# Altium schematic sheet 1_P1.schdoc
size 307 x 218 mm; Symbol: Drawing-Symbol_A4; Device: Drawing-Symbol_A4; @Project Name: PBT_PCB; @Page Count: 1; @Update Date: 2026-08-30; @Create Date: 2026-01-09; @Schematic Name: Schematic1_2; @Page No: 1; @Page Name: P1; Company: EasyEDA.com; Version: V1.0; Page Size: A4; @Create Time: 14:17:53; @Update Time: 10:38:52; Width: 1170; Height: 825; Region Start: 1; X Region Count: 6; Y Region Count: 4; Blade Width: 10; Title Block Position: 3; @Board Name: Sensor board_2s_lp
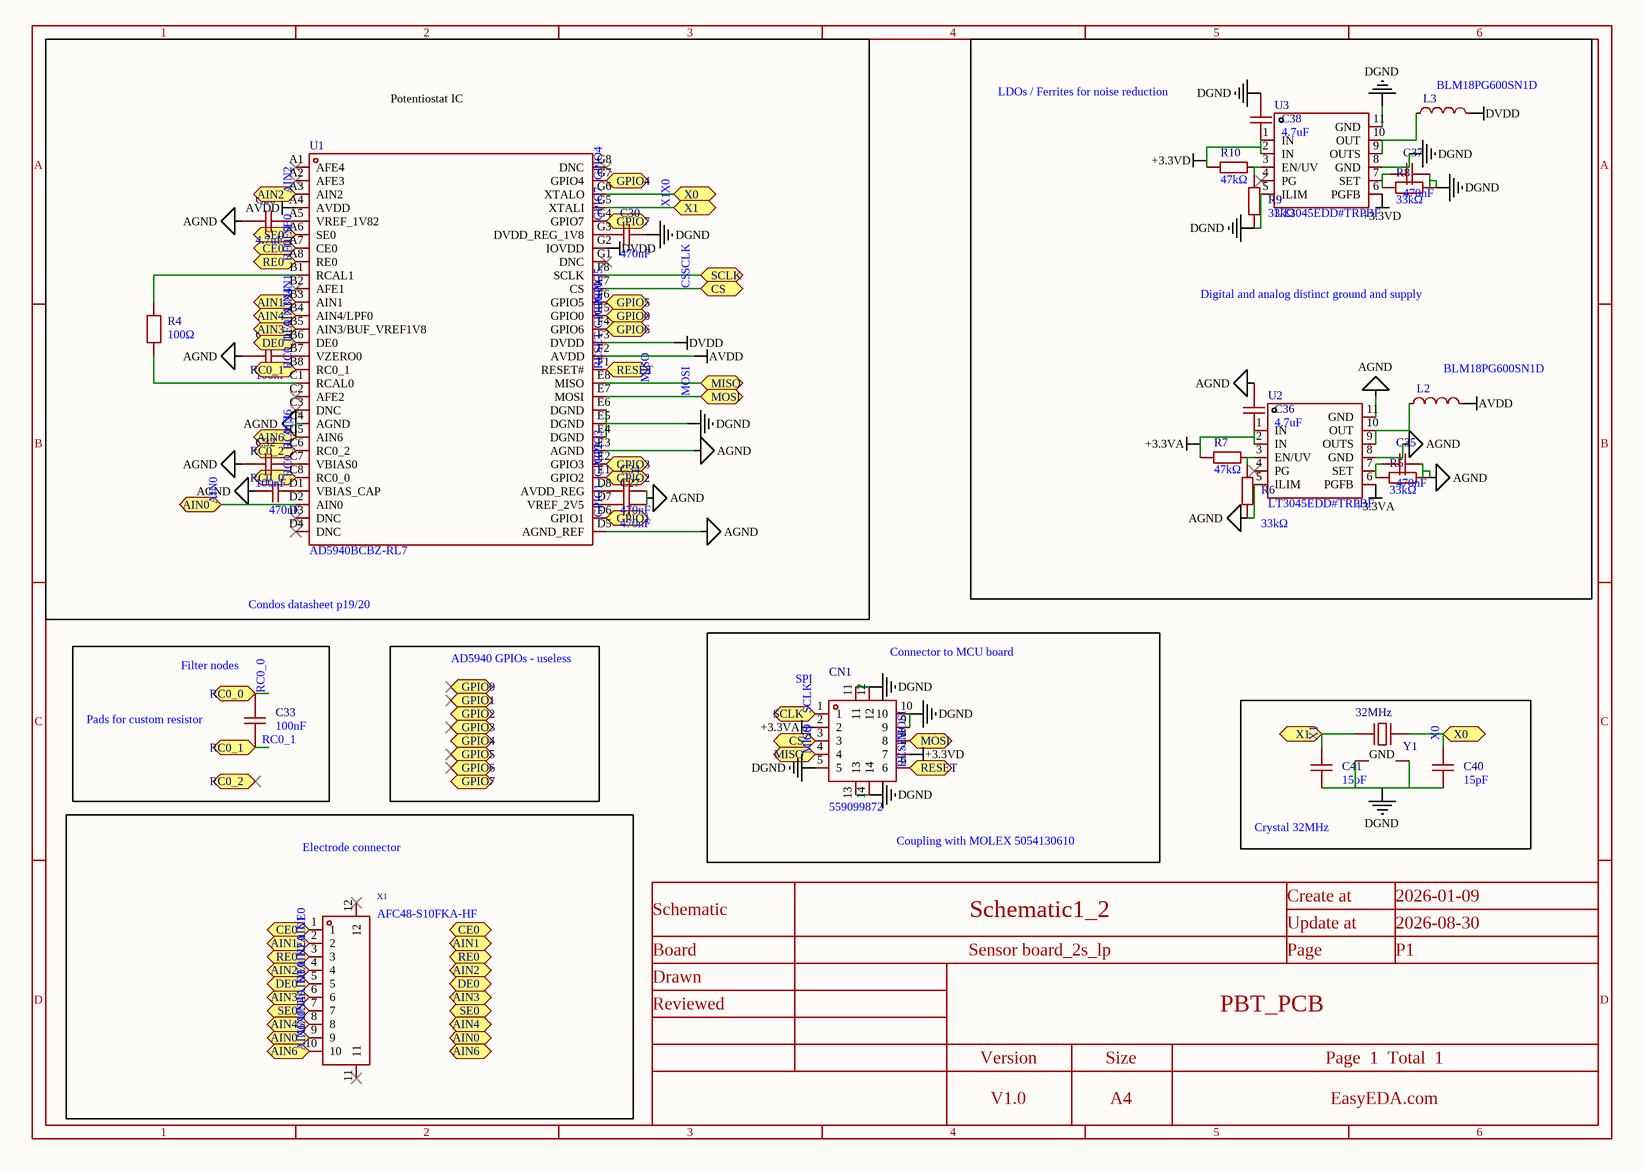
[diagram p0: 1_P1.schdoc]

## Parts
C27  470nF  [C0603]
C28  4.7uF  [C0402]
C29  470nF  [C0603]
C30  470nF  [C0603]
C31  100nF  [C0402]
C32  100nF  [C0402]
C33  100nF  [C0402]
C34  470nF  [C0603]
C35  470nF  [C0603]
C36  4.7uF  [C0402]
C37  470nF  [C0603]
C38  4.7uF  [C0402]
C40  15pF  [C0402]
C41  15pF  [C0402]
CN1  559099872  [CONN-SMD_559099872]
L2  BLM18PG600SN1D  [L0603]
L3  BLM18PG600SN1D  [L0603]
R4  100Ω  [R0603]
R5  33kΩ  [R0402]
R6  33kΩ  [R0402]
R7  47kΩ  [R0402]
R8  33kΩ  [R0402]
R9  33kΩ  [R0402]
R10  47kΩ  [R0402]
U1  AD5940BCBZ-RL7  [BGA-56_L4.2-W3.6-R8-C7-P0.40-TL]
U2  LT3045EDD#TRPBF  [DFN-10_L3.0-W3.0-P0.50-BL-EP]
U3  LT3045EDD#TRPBF  [DFN-10_L3.0-W3.0-P0.50-BL-EP]
X1  AFC48-S10FKA-HF  [FPC-SMD_AFC48-S10FKA-HF]
Y1  32MHz  [CRYSTAL-SMD_4P-L2.0-W1.6-BL]

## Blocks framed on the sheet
Crystal 32MHz: C40 C41 Y1
Electrode connector: X1

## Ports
AIN0 (bidir), AIN1 (bidir), AIN2 (bidir), AIN3 (bidir), AIN4 (bidir), AIN6 (bidir), CE0 (bidir), CS (bidir), DE0 (bidir), GPIO0 (bidir), GPIO1 (bidir), GPIO2 (bidir), GPIO3 (bidir), GPIO4 (bidir), GPIO5 (bidir), GPIO6 (bidir), GPIO7 (bidir), MISO (bidir), MOSI (bidir), RC0_0 (bidir), RC0_1 (bidir), RC0_2 (bidir), RE0 (bidir), RESET (bidir), SCLK (bidir), SE0 (bidir), X0 (bidir), X1 (bidir)

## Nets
+3.3VA: C36.2 CN1.2 R7.2 U2.1(IN) U2.2(IN) U2.6(PGFB)
+3.3VD: C38.2 CN1.7 R10.2 U3.1(IN) U3.2(IN) U3.6(PGFB)
AGND: C27.2 C28.1 C29.1 C31.1 C32.1 C34.2 C35.2 C36.1 R5.2 R6.1 U1.C4(AGND) U1.D5(AGND_REF) U1.E3(AGND) U2.5(ILIM) U2.8(GND) U2.11(GND)
AVDD: L2.2 U1.A4(AVDD) U1.F2(AVDD)
DGND: C30.2 C37.2 C38.1 C40.2 C41.2 CN1.5 CN1.9 CN1.10 CN1.11 CN1.12 CN1.13 CN1.14 R8.2 R9.1 U1.E4(DGND) U1.E5(DGND) U1.E6(DGND) U3.5(ILIM) U3.8(GND) U3.11(GND) Y1.2(GND) Y1.4(GND)
DVDD: L3.2 U1.F3(DVDD) U1.G2(IOVDD)
AIN0: U1.D2(AIN0) X1.9 ; port AIN0
AIN1: U1.B3(AIN1) X1.2 ; port AIN1
AIN2: U1.A3(AIN2) X1.4 ; port AIN2
AIN3: U1.B5(AIN3/BUF_VREF1V8) X1.6 ; port AIN3
AIN4: U1.B4(AIN4/LPF0) X1.8 ; port AIN4
AIN6: U1.C5(AIN6) X1.10 ; port AIN6
CE0: U1.A7(CE0) X1.1 ; port CE0
CS: CN1.3 U1.F7(CS) ; port CS
DE0: U1.B6(DE0) X1.5 ; port DE0
GPIO0: U1.F5(GPIO0) ; port GPIO0
GPIO1: U1.D6(GPIO1) ; port GPIO1
GPIO2: U1.E1(GPIO2) ; port GPIO2
GPIO3: U1.E2(GPIO3) ; port GPIO3
GPIO4: U1.G7(GPIO4) ; port GPIO4
GPIO5: U1.F6(GPIO5) ; port GPIO5
GPIO6: U1.F4(GPIO6) ; port GPIO6
GPIO7: U1.G4(GPIO7) ; port GPIO7
MISO: CN1.4 U1.E8(MISO) ; port MISO
MOSI: CN1.8 U1.E7(MOSI) ; port MOSI
RC0_0: C33.1 U1.C8(RC0_0) ; port RC0_0
RC0_1: C33.2 U1.B8(RC0_1) ; port RC0_1
RC0_2: U1.C6(RC0_2) ; port RC0_2
RE0: U1.A8(RE0) X1.3 ; port RE0
RESET: CN1.6 U1.F1(RESET#) ; port RESET
SCLK: CN1.1 U1.F8(SCLK) ; port SCLK
SE0: U1.A6(SE0) X1.7 ; port SE0
X0: C40.1 U1.G6(XTALO) Y1.3 ; port X0
X1: C41.1 U1.G5(XTALI) Y1.1 ; port X1
NetC27_1: C27.1 U1.D7(VREF_2V5)
NetC28_2: C28.2 U1.A5(VREF_1V82)
NetC29_2: C29.2 U1.D1(VBIAS_CAP)
NetC30_1: C30.1 U1.G3(DVDD_REG_1V8)
NetC31_2: C31.2 U1.B7(VZERO0)
NetC32_2: C32.2 U1.C7(VBIAS0)
NetC34_1: C34.1 U1.D8(AVDD_REG)
NetC35_1: C35.1 R5.1 U2.7(SET)
NetC37_1: C37.1 R8.1 U3.7(SET)
NetL2_1: L2.1 U2.9(OUTS) U2.10(OUT)
NetL3_1: L3.1 U3.9(OUTS) U3.10(OUT)
NetR4_1: R4.1 U1.B1(RCAL1)
NetR4_2: R4.2 U1.C1(RCAL0)
NetR6_2: R6.2 R7.1 U2.3(EN/UV)
NetR9_2: R9.2 R10.1 U3.3(EN/UV)

Not connected (* = marked no-connect by the designer): U1 A1(AFE4)* A2(AFE3)* B2(AFE1)* C2(AFE2)* C3(DNC)* D3(DNC)* D4(DNC)* G1(DNC)* G8(DNC)*; U2 4(PG)*; U3 4(PG)*; X1 11* 12*

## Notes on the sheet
- Potentiostat IC
- LDOs / Ferrites for noise reduction
- Digital and analog distinct ground and supply
- Condos datasheet p19/20
- (near CN1) Connector to MCU board
- (near C33) Filter nodes
- AD5940 GPIOs - useless
- (near CN1) SPI
- (near C33) Pads for custom resistor
- Coupling with MOLEX 5054130610

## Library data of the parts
C27 C29 C30 C34 C35 C37 = CL10B474KA8NNNC: Manufacturer: SAMSUNG(三星); Add into BOM: yes; Tolerance: ±10%; Voltage Rating: 25V; Temperature Coefficient: X7R
C28 C36 C38 = CL05A475MP5NRNC: Manufacturer: SAMSUNG(三星); Add into BOM: yes; Tolerance: ±20%; Voltage Rating: 10V; Temperature Coefficient: X5R
C31-C33 = CL05B104KO5NNNC: Manufacturer: SAMSUNG(三星); Add into BOM: yes; Tolerance: ±10%; Voltage Rating: 16V; Temperature Coefficient: X7R
C40 C41 = 0402CG150J500NT: Manufacturer: FH(风华); Add into BOM: yes; Tolerance: ±5%; Voltage Rating: 50V; Temperature Coefficient: C0G
CN1 = 559099872: Manufacturer: MOLEX; Add into BOM: yes; Pitch: 0.4mm; Current Rating: 300mA; Voltage Rating: 50V; System Fit Height: 1.5mm
L2 L3 = BLM18PG600SN1D: Manufacturer: muRata(村田); Add into BOM: yes; Impedance @ Frequency: 60Ω@100MHz; Tolerance: ±25%; DC Resistance: 100mΩ; Current Rating: 1A; Circuits: 1
R4 = PTFR0603Q100RN9: Manufacturer: RESI(开步睿思); Add into BOM: yes; Tolerance: ±0.02%; Temperature Coefficient: ±10ppm/℃
R5 R6 R8 R9 = 0402WGF3302TCE: Manufacturer: UNI-ROYAL(厚声); Add into BOM: yes; Tolerance: ±1%; Temperature Coefficient: ±100ppm/℃
R7 R10 = 0402WGF4702TCE: Manufacturer: UNI-ROYAL(厚声); Add into BOM: yes; Tolerance: ±1%; Power(Watts): 62.5mW; Voltage-Supply(Max): 50V; Temperature Coefficient: ±100ppm/℃
U1 = AD5940BCBZ-RL7: Manufacturer: ADI(亚德诺); Add into BOM: yes; Supply Voltage: 2.8V~3.6V
U2 U3 = LT3045EDD#TRPBF_C514420: Manufacturer: ADI(亚德诺); Add into BOM: yes; Output Type: Adjustable; Voltage - Supply: 20V; Output Voltage: 0V~15V; Output Current: 500mA; Power Supply Rejection Ratio (PSRR): 76dB@(1MHz); Voltage Dropout: 350mV@(500mA); standby current: 2.2mA; Noise: 0.8uVrms; Output Configuration: Positive; Number of Outputs: 1
X1 = AFC48-S10FKA-HF: Manufacturer: JS(钜硕电子); Add into BOM: yes; Locking Feature: Clamshell; Number of Contacts: 10P; Pitch: 0.5mm; FFC, FCB Thickness: 0.3mm
Y1 = XL7EL89CKI-111YLC-32M: Manufacturer: YXC(扬兴晶振); Symbol: Abracon Crystal ABM10; Add into BOM: yes; Crystal Type: Surface Mount Crystal; Normal temperature Frequency Tolerance: ±10ppm; Frequency Stability(Full temperature range): ±20ppm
